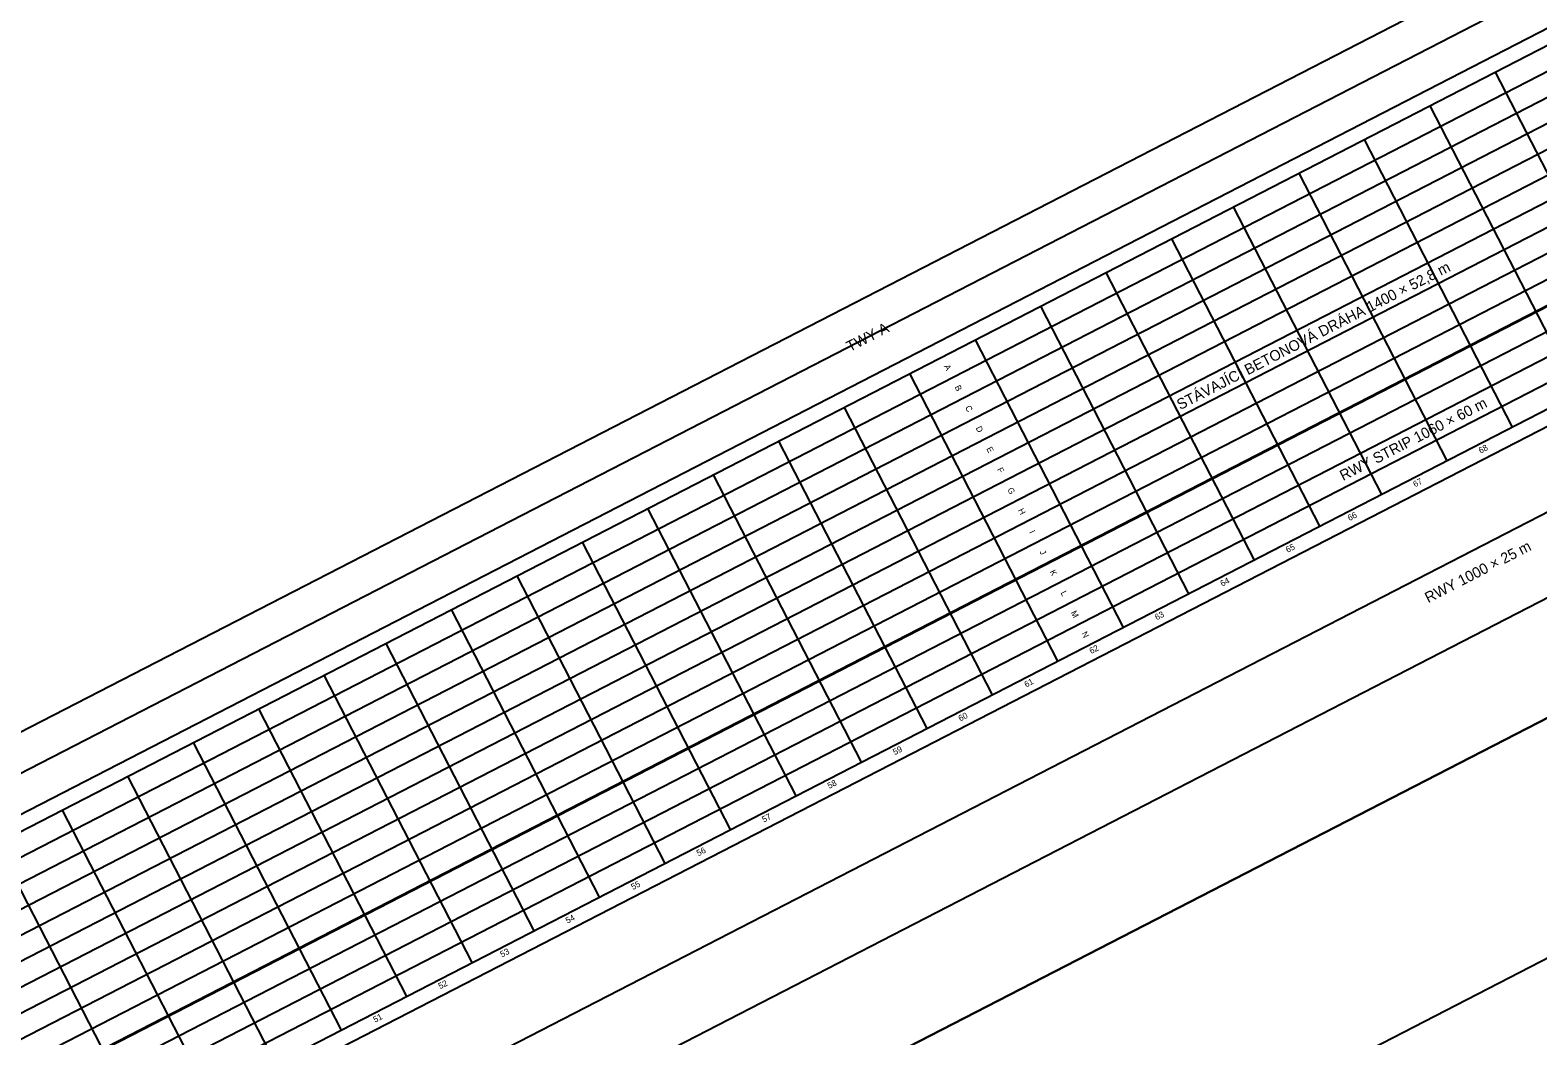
# Model space of a CAD drawing. Extents: x -886320 to -884760, y -1024172 to -1023483.
# Drawn here: x -885521.7 to -885274.6, y -1023897 to -1023732.2 of the extents above; entities that cross this region are included whole.
import ezdxf

# ---------------------------------------------------------------- set-up
doc = ezdxf.new("R2010")
doc.units = 0
for name, color, linetype in [('AGA__Netisknout', 7, 'Continuous'), ('Stavajici_betonova_draha', 7, 'Continuous'), ('Stavajici_betonova_draha_osa', 7, 'Continuous'), ('Stavajici_betonova_draha_popis', 7, 'Continuous'), ('Stavajici_betonova_draha_Popis desky', 7, 'Continuous'), ('Stavajici_betonova_draha_Spára', 7, 'Continuous'), ('Stavajici_drahovy_system', 7, 'Continuous'), ('Stavajici_drahovy_system_osy', 7, 'Continuous'), ('Stavajici_drahovy_system_popis', 7, 'Continuous'), ('Stavajici_drahovy_system_RWY_strip', 7, 'Continuous'), ('Stavajici_drahovy_system_TWY', 7, 'Continuous'), ('Stavajici_drahovy_system_TWY_osy', 7, 'Continuous'), ('Stavajici_drahovy_system_TWY_popis', 7, 'Continuous')]:
    doc.layers.add(name, color=color, linetype=linetype)

msp = doc.modelspace()

# ---------------------------------------------------------------- linework, layer by layer
at = {"layer": 'AGA__Netisknout'}
msp.add_line((-886017.78, -1024147.99), (-884773.13, -1023507.02), dxfattribs=at)
at = {"layer": 'Stavajici_betonova_draha'}
for p, q in [((-886029.69, -1024124.32), (-884785.04, -1023483.35)), ((-886029.69, -1024124.32), (-884785.04, -1023483.35)), ((-886005.42, -1024171.44), (-884760.77, -1023530.47)), ((-886005.42, -1024171.44), (-884760.77, -1023530.47))]:
    msp.add_line(p, q, dxfattribs=at)
at = {"layer": 'Stavajici_betonova_draha_osa'}
msp.add_line((-886017.55, -1024147.88), (-884772.9, -1023506.91), dxfattribs=at)
at = {"layer": 'Stavajici_betonova_draha_Spára'}
for p, q in [((-886029.91, -1024124.43), (-884785.26, -1023483.46)), ((-886028.18, -1024127.8), (-884783.53, -1023486.82)), ((-886026.44, -1024131.16), (-884781.79, -1023490.19)), ((-886024.71, -1024134.53), (-884780.06, -1023493.56)), ((-886022.98, -1024137.89), (-884778.33, -1023496.92)), ((-886021.24, -1024141.26), (-884776.59, -1023500.29)), ((-886019.51, -1024144.63), (-884774.86, -1023503.65)), ((-886016.04, -1024151.36), (-884771.39, -1023510.39)), ((-886014.31, -1024154.72), (-884769.66, -1023513.75)), ((-886012.58, -1024158.09), (-884767.93, -1023517.12)), ((-886010.84, -1024161.46), (-884766.19, -1023520.48)), ((-886009.11, -1024164.82), (-884764.46, -1023523.85)), ((-886007.38, -1024168.19), (-884762.73, -1023527.21)), ((-886005.64, -1024171.55), (-884760.99, -1023530.58)), ((-885281.6, -1023739.06), (-885257.33, -1023786.19)), ((-885292.33, -1023744.59), (-885268.06, -1023791.71)), ((-885303.06, -1023750.12), (-885278.79, -1023797.24)), ((-885313.79, -1023755.64), (-885289.52, -1023802.76)), ((-885324.52, -1023761.17), (-885300.25, -1023808.29)), ((-885334.66, -1023766.39), (-885310.39, -1023813.51)), ((-885345.39, -1023771.92), (-885321.12, -1023819.04)), ((-885356.12, -1023777.44), (-885331.85, -1023824.56)), ((-885366.85, -1023782.97), (-885342.58, -1023830.09)), ((-885377.58, -1023788.49), (-885353.31, -1023835.61)), ((-885388.31, -1023794.02), (-885364.04, -1023841.14)), ((-885399.04, -1023799.54), (-885374.77, -1023846.67)), ((-885409.77, -1023805.07), (-885385.5, -1023852.19)), ((-885420.5, -1023810.59), (-885396.23, -1023857.72)), ((-885431.23, -1023816.12), (-885406.96, -1023863.24)), ((-885441.96, -1023821.65), (-885417.69, -1023868.77)), ((-885452.69, -1023827.17), (-885428.42, -1023874.29)), ((-885463.42, -1023832.7), (-885439.15, -1023879.82)), ((-885473.55, -1023837.92), (-885449.29, -1023885.04)), ((-885484.28, -1023843.44), (-885460.02, -1023890.57)), ((-885495.01, -1023848.97), (-885470.75, -1023896.09)), ((-885505.74, -1023854.49), (-885481.48, -1023901.62)), ((-885516.47, -1023860.02), (-885492.2, -1023907.14)), ((-885527.2, -1023865.55), (-885502.93, -1023912.67))]:
    msp.add_line(p, q, dxfattribs=at)
at = {"layer": 'Stavajici_drahovy_system'}
for p, q in [((-885721.56, -1024028.07), (-884864.53, -1023586.71)), ((-885726.12, -1024058.54), (-884837.08, -1023600.7)), ((-885744.78, -1024087.83), (-884802.4, -1023602.52)), ((-885728.75, -1024118.95), (-884786.38, -1023633.64))]:
    msp.add_line(p, q, dxfattribs=at)
at = {"layer": 'Stavajici_drahovy_system_osy'}
msp.add_line((-885731.84, -1024047.42), (-884842.81, -1023589.59), dxfattribs=at)
at = {"layer": 'Stavajici_drahovy_system_RWY_strip'}
for p, q in [((-885772.25, -1024034.49), (-884829.87, -1023549.18)), ((-884802.4, -1023602.52), (-885744.78, -1024087.83))]:
    msp.add_line(p, q, dxfattribs=at)
at = {"layer": 'Stavajici_drahovy_system_TWY'}
for p, q in [((-885887.27, -1024034.67), (-884885.91, -1023518.99)), ((-885748.12, -1023976.51), (-884891.09, -1023535.15))]:
    msp.add_line(p, q, dxfattribs=at)
at = {"layer": 'Stavajici_drahovy_system_TWY_osy'}
msp.add_line((-885886.7, -1024041.13), (-884883.17, -1023524.32), dxfattribs=at)

# ---------------------------------------------------------------- texts
at = {"layer": 'Stavajici_betonova_draha_popis'}
msp.add_text('STÁVAJÍCÍ BETONOVÁ DRÁHA 1400 × 52,8 m', height=1.75, rotation=27.2477, dxfattribs=at).set_placement((-885333.22, -1023794.48))
at = {"layer": 'Stavajici_betonova_draha_Popis desky'}
for s, rotation, p in [('A', 297.2477, (-885371.97, -1023787.3)), ('B', 297.2477, (-885370.22, -1023790.69)), ('C', 297.2477, (-885368.5, -1023794.03)), ('D', 297.2477, (-885366.77, -1023797.4)), ('E', 297.2477, (-885365.02, -1023800.79)), ('68', 27.2477, (-885284.01, -1023801.61)), ('F', 297.2477, (-885363.27, -1023804.18)), ('67', 27.2477, (-885294.74, -1023807.14)), ('G', 297.2477, (-885361.58, -1023807.47)), ('H', 297.2477, (-885359.83, -1023810.88)), ('66', 27.2477, (-885305.47, -1023812.67)), ('I', 297.2477, (-885357.98, -1023814.47)), ('65', 27.2477, (-885315.62, -1023817.89)), ('J', 297.2477, (-885356.3, -1023817.72)), ('K', 297.2477, (-885354.63, -1023820.96)), ('64', 27.2477, (-885326.34, -1023823.41)), ('L', 297.2477, (-885352.86, -1023824.4)), ('M', 297.2477, (-885351.19, -1023827.65)), ('63', 27.2477, (-885337.07, -1023828.94)), ('N', 297.2477, (-885349.43, -1023831.07)), ('62', 27.2477, (-885347.8, -1023834.46)), ('61', 27.2477, (-885358.46, -1023839.95)), ('60', 27.2477, (-885369.26, -1023845.52)), ('59', 27.2477, (-885379.99, -1023851.04)), ('58', 27.2477, (-885390.72, -1023856.57)), ('57', 27.2477, (-885401.45, -1023862.09)), ('56', 27.2477, (-885412.18, -1023867.62)), ('55', 27.2477, (-885422.91, -1023873.15)), ('54', 27.2477, (-885433.64, -1023878.67)), ('53', 27.2477, (-885444.37, -1023884.2)), ('52', 27.2477, (-885454.5, -1023889.41)), ('51', 27.2477, (-885465.17, -1023894.9))]:
    msp.add_text(s, height=1, rotation=rotation, dxfattribs=at).set_placement(p)
at = {"layer": 'Stavajici_drahovy_system_popis'}
msp.add_text('RWY 1000 × 25 m', height=1.75, rotation=27.2477, dxfattribs=at).set_placement((-885292.57, -1023826.13))
at = {"layer": 'Stavajici_drahovy_system_RWY_strip'}
msp.add_text('RWY STRIP 1060 × 60 m', height=1.75, rotation=27.2477, dxfattribs=at).set_placement((-885306.51, -1023806.11))
at = {"layer": 'Stavajici_drahovy_system_TWY_popis'}
msp.add_text('TWY A', height=1.75, rotation=27.2477, dxfattribs=at).set_placement((-885387.36, -1023784.96))

doc.saveas('drawing.dxf')
